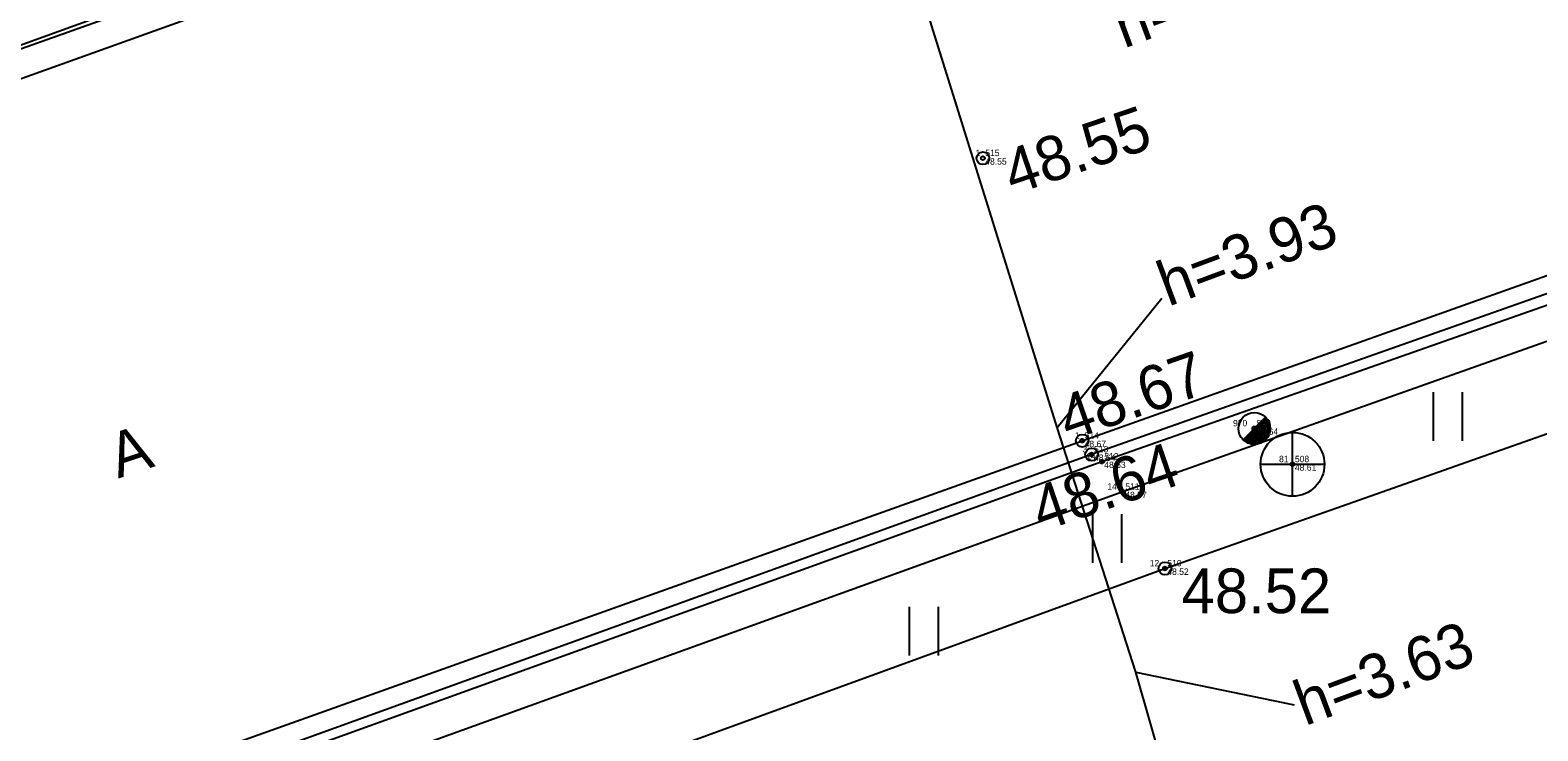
# Model space of a CAD drawing. Extents: x 543497 to 552146, y 6567125 to 6579845.
# Drawn here: x 545917.19 to 545940.79, y 6577629.81 to 6577640.78 of the extents above; entities that cross this region are included whole.
import ezdxf

# ---------------------------------------------------------------- set-up
doc = ezdxf.new("R2010")
doc.units = 0
for name, color, linetype in [('xref_Kangru tee 1_geodeesia$0$ABIJOONIS', 7, 'Continuous'), ('xref_Kangru tee 1_geodeesia$0$HALJASTUS', 7, 'Continuous'), ('xref_Kangru tee 1_geodeesia$0$korgus-EH2000', 7, 'Continuous'), ('xref_Kangru tee 1_geodeesia$0$Liiklus', 7, 'Continuous'), ('xref_Kangru tee 1_geodeesia$0$mootkood', 7, 'Continuous'), ('xref_Kangru tee 1_geodeesia$0$MOOTKORG-eh2000', 7, 'Continuous'), ('xref_Kangru tee 1_geodeesia$0$mootmpunkt', 7, 'Continuous'), ('xref_Kangru tee 1_geodeesia$0$MOOTNR', 7, 'Continuous'), ('xref_Kangru tee 1_geodeesia$0$MOOTPIIR', 7, 'Continuous'), ('xref_Kangru tee 1_geodeesia$0$MPKAABEL', 7, 'Continuous'), ('xref_Kangru tee 1_geodeesia$0$Post', 7, 'Continuous'), ('xref_Kangru tee 1_geodeesia$0$SKKAEV', 7, 'Continuous'), ('xref_Kangru tee 1_geodeesia$0$TEE', 7, 'Continuous')]:
    doc.layers.add(name, color=color, linetype=linetype)

# ---------------------------------------------------------------- blocks, each defined once
blk = doc.blocks.new('xref_Kangru tee 1_geodeesia$0$KAKAEV')
for p, q in [((0, -1), (0, 1)), ((-1, 0), (1, 0))]:
    blk.add_line(p, q)
blk.add_circle((0, 0), 1)
blk = doc.blocks.new('xref_Kangru tee 1_geodeesia$0$plpost')
blk.add_line((-0.354, -0.353), (0.353, 0.354))
blk.add_circle((0, 0), 0.5)
for radius, start, end in [(0.45, 224.8541, 45.0356), (0.4, 224.8427, 45.047), (0.35, 224.8281, 45.0616), (0.3, 224.8087, 45.081), (0.25, 224.7814, 45.1083), (0.2, 224.7406, 45.1491), (0.15, 224.6725, 45.2172), (0.1, 224.5363, 45.3534), (0.05, 224.1278, 45.7619)]:
    blk.add_arc((0, 0), radius, start, end)
blk = doc.blocks.new('xref_Kangru tee 1_geodeesia$0$hein')
for p, q in [((-0.455, 0.761), (-0.455, -0.761)), ((0.455, 0.761), (0.455, -0.761))]:
    blk.add_line(p, q)

msp = doc.modelspace()

# ---------------------------------------------------------------- linework, layer by layer
at = {"layer": 'xref_Kangru tee 1_geodeesia$0$ABIJOONIS'}
for p, q in [((545933.268, 6577634.56), (545934.909, 6577636.586)), ((545934.498, 6577630.73), (545936.979, 6577630.218))]:
    msp.add_line(p, q, dxfattribs=at)
at = {"layer": 'xref_Kangru tee 1_geodeesia$0$korgus-EH2000'}
for centre in [(545932.106, 6577638.776), (545933.661, 6577634.352), (545933.808, 6577634.136), (545934.956, 6577632.352)]:
    msp.add_circle(centre, 0.1, dxfattribs=at)
at = {"layer": 'xref_Kangru tee 1_geodeesia$0$Liiklus'}
for points in [[(546140.387, 6577713.403), (546116.908, 6577706.504), (546094.508, 6577699.709), (546071.341, 6577692.568), (546048.377, 6577685.322), (546024.051, 6577677.467), (546000.007, 6577669.497), (545974.577, 6577660.93), (545953.828, 6577653.707), (545929.813, 6577645.16), (545906.85, 6577636.866)], [(545910.777, 6577625.663), (545933.969, 6577634.025), (545958.008, 6577642.491), (545978.611, 6577649.687), (546003.506, 6577658.099), (546027.939, 6577666.219), (546052.189, 6577674.015), (546074.504, 6577681.116), (546097.636, 6577688.197), (546120.931, 6577695.189), (546144.399, 6577702.07)], [(546144.547, 6577701.652), (546121.068, 6577694.663), (546097.922, 6577687.788), (546074.601, 6577680.633), (546052.33, 6577673.558), (546028.25, 6577665.754), (546003.455, 6577657.552), (545979.103, 6577649.278), (545958.136, 6577642.016), (545934.298, 6577633.553), (545911.013, 6577625.148)]]:
    msp.add_lwpolyline(points, dxfattribs=at)
at = {"layer": 'xref_Kangru tee 1_geodeesia$0$mootmpunkt'}
for centre in [(545932.106, 6577638.776), (545936.355, 6577634.545), (545933.661, 6577634.352), (545933.808, 6577634.136), (545933.969, 6577634.025), (545936.953, 6577633.983), (545934.298, 6577633.553), (545934.956, 6577632.352)]:
    msp.add_circle(centre, 0.03, dxfattribs=at)
at = {"layer": 'xref_Kangru tee 1_geodeesia$0$MOOTPIIR'}
msp.add_lwpolyline([(545911.475, 6577623.795), (545934.956, 6577632.352), (545958.425, 6577640.634), (545979.717, 6577647.979)], dxfattribs=at)
at = {"layer": 'xref_Kangru tee 1_geodeesia$0$MPKAABEL'}
msp.add_lwpolyline([(545940.128, 6577606.54), (545939.248, 6577612.58), (545937.798, 6577618.69), (545937.158, 6577621.46), (545934.498, 6577630.73), (545933.268, 6577634.56), (545930.818, 6577642.42), (545930.428, 6577645.32), (545929.638, 6577649.21), (545928.438, 6577653.24), (545926.545, 6577660.97), (545926.248, 6577664.92), (545925.358, 6577668.93), (545923.709, 6577674.241), (545922.889, 6577675.319)], dxfattribs=at)
msp.add_lwpolyline([(545940.128, 6577606.54), (545939.248, 6577612.58), (545937.798, 6577618.69), (545937.158, 6577621.46), (545934.498, 6577630.73), (545933.268, 6577634.56), (545930.818, 6577642.42), (545930.428, 6577645.32), (545929.638, 6577649.21), (545928.438, 6577653.24), (545926.545, 6577660.97), (545926.248, 6577664.92), (545925.358, 6577668.93), (545923.709, 6577674.241), (545922.889, 6577675.319)], dxfattribs=at)
at = {"layer": 'xref_Kangru tee 1_geodeesia$0$TEE'}
for points in [[(545906.85, 6577636.866), (545929.889, 6577645.059), (545953.872, 6577653.571), (545974.605, 6577661.456), (545999.934, 6577669.987), (546023.789, 6577677.871), (546048.093, 6577685.795), (546071.324, 6577693.114), (546094.183, 6577700.122), (546117.024, 6577707.078), (546140.081, 6577713.851)], [(545907.046, 6577636.431), (545930.044, 6577644.691), (545953.99, 6577653.148), (545974.87, 6577660.403), (546000.141, 6577668.988), (546024.289, 6577677), (546048.596, 6577684.894), (546071.539, 6577692.067), (546094.678, 6577699.21), (546117.101, 6577706.011), (546140.733, 6577712.948)], [(545910.584, 6577626.12), (545933.661, 6577634.352), (545957.791, 6577642.935), (545978.471, 6577649.978), (546003.394, 6577658.646), (546027.796, 6577666.689), (546052.06, 6577674.499), (546074.348, 6577681.538), (546097.453, 6577688.664), (546120.761, 6577695.678), (546144.19, 6577702.591)], [(546144.343, 6577702.205), (546120.903, 6577695.427), (546097.566, 6577688.331), (546074.414, 6577681.298), (546052.115, 6577674.191), (546027.872, 6577666.376), (546003.492, 6577658.359), (545978.595, 6577649.764), (545957.931, 6577642.653), (545933.808, 6577634.136), (545910.722, 6577625.792)]]:
    msp.add_lwpolyline(points, dxfattribs=at)

# ---------------------------------------------------------------- block references
at = {"layer": 'xref_Kangru tee 1_geodeesia$0$HALJASTUS', "xscale": 0.5, "yscale": 0.5}
for p in [(545939.381, 6577634.73), (545934.047, 6577632.82), (545931.179, 6577631.369)]:
    msp.add_blockref('xref_Kangru tee 1_geodeesia$0$hein', p, dxfattribs=at)
at = {"layer": 'xref_Kangru tee 1_geodeesia$0$Post', "xscale": 0.5, "yscale": 0.5}
msp.add_blockref('xref_Kangru tee 1_geodeesia$0$plpost', (545936.355, 6577634.545), dxfattribs=at)
at = {"layer": 'xref_Kangru tee 1_geodeesia$0$SKKAEV', "xscale": 0.5, "yscale": 0.5}
msp.add_blockref('xref_Kangru tee 1_geodeesia$0$KAKAEV', (545936.953, 6577633.983), dxfattribs=at)

# ---------------------------------------------------------------- texts
at = {"layer": 'xref_Kangru tee 1_geodeesia$0$ABIJOONIS'}
for s, rotation, p in [('h=4.23', 20.3749, (545934.313, 6577640.491)), ('h=3.93', 20.355, (545935.006, 6577636.448)), ('h=3.63', 20.4086, (545937.147, 6577629.881))]:
    msp.add_text(s, height=0.7, rotation=rotation, dxfattribs=at).set_placement(p)
at = {"layer": 'xref_Kangru tee 1_geodeesia$0$korgus-EH2000'}
for s, rotation, p in [(' 48.55 ', 18.7791, (545932.331, 6577638.113)), (' 48.67 ', 19.1955, (545933.197, 6577634.258)), (' 48.64 ', 18.9603, (545932.771, 6577632.836))]:
    msp.add_text(s, height=0.7, rotation=rotation, dxfattribs=at).set_placement(p)
msp.add_text(' 48.52 ', height=0.7, dxfattribs=at).set_placement((545934.956, 6577631.652))
at = {"layer": 'xref_Kangru tee 1_geodeesia$0$mootkood'}
for s, p in [(' 1', (545931.954, 6577638.809)), (' 1', (545933.509, 6577634.385)), (' 970', (545935.984, 6577634.578)), (' 3', (545933.627, 6577634.169)), (' 14', (545933.688, 6577634.058)), (' 81', (545936.705, 6577634.016)), (' 14', (545934.017, 6577633.586)), (' 12', (545934.68, 6577632.385))]:
    msp.add_text(s, height=0.1, dxfattribs=at).set_placement(p)
at = {"layer": 'xref_Kangru tee 1_geodeesia$0$MOOTKORG-eh2000'}
for s, p in [(' 48.55', (545932.106, 6577638.676)), (' 48.64', (545936.355, 6577634.445)), (' 48.67', (545933.661, 6577634.252)), (' 48.64', (545933.808, 6577634.036)), (' 48.63', (545933.969, 6577633.925)), (' 48.61', (545936.953, 6577633.883)), (' 48.57', (545934.298, 6577633.453)), (' 48.52', (545934.956, 6577632.252))]:
    msp.add_text(s, height=0.1, dxfattribs=at).set_placement(p)
at = {"layer": 'xref_Kangru tee 1_geodeesia$0$MOOTNR'}
for s, p in [(' 515', (545932.106, 6577638.809)), (' 514', (545933.661, 6577634.385)), (' 509', (545936.355, 6577634.578)), (' 513', (545933.808, 6577634.169)), (' 512', (545933.969, 6577634.058)), (' 508', (545936.953, 6577634.016)), (' 511', (545934.298, 6577633.586)), (' 510', (545934.956, 6577632.385))]:
    msp.add_text(s, height=0.1, dxfattribs=at).set_placement(p)
at = {"layer": 'xref_Kangru tee 1_geodeesia$0$TEE'}
msp.add_text('A', height=0.7, rotation=18.3444, dxfattribs=at).set_placement((545918.567, 6577633.758))

doc.saveas('drawing.dxf')
